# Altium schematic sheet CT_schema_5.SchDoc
size 388 x 258 mm
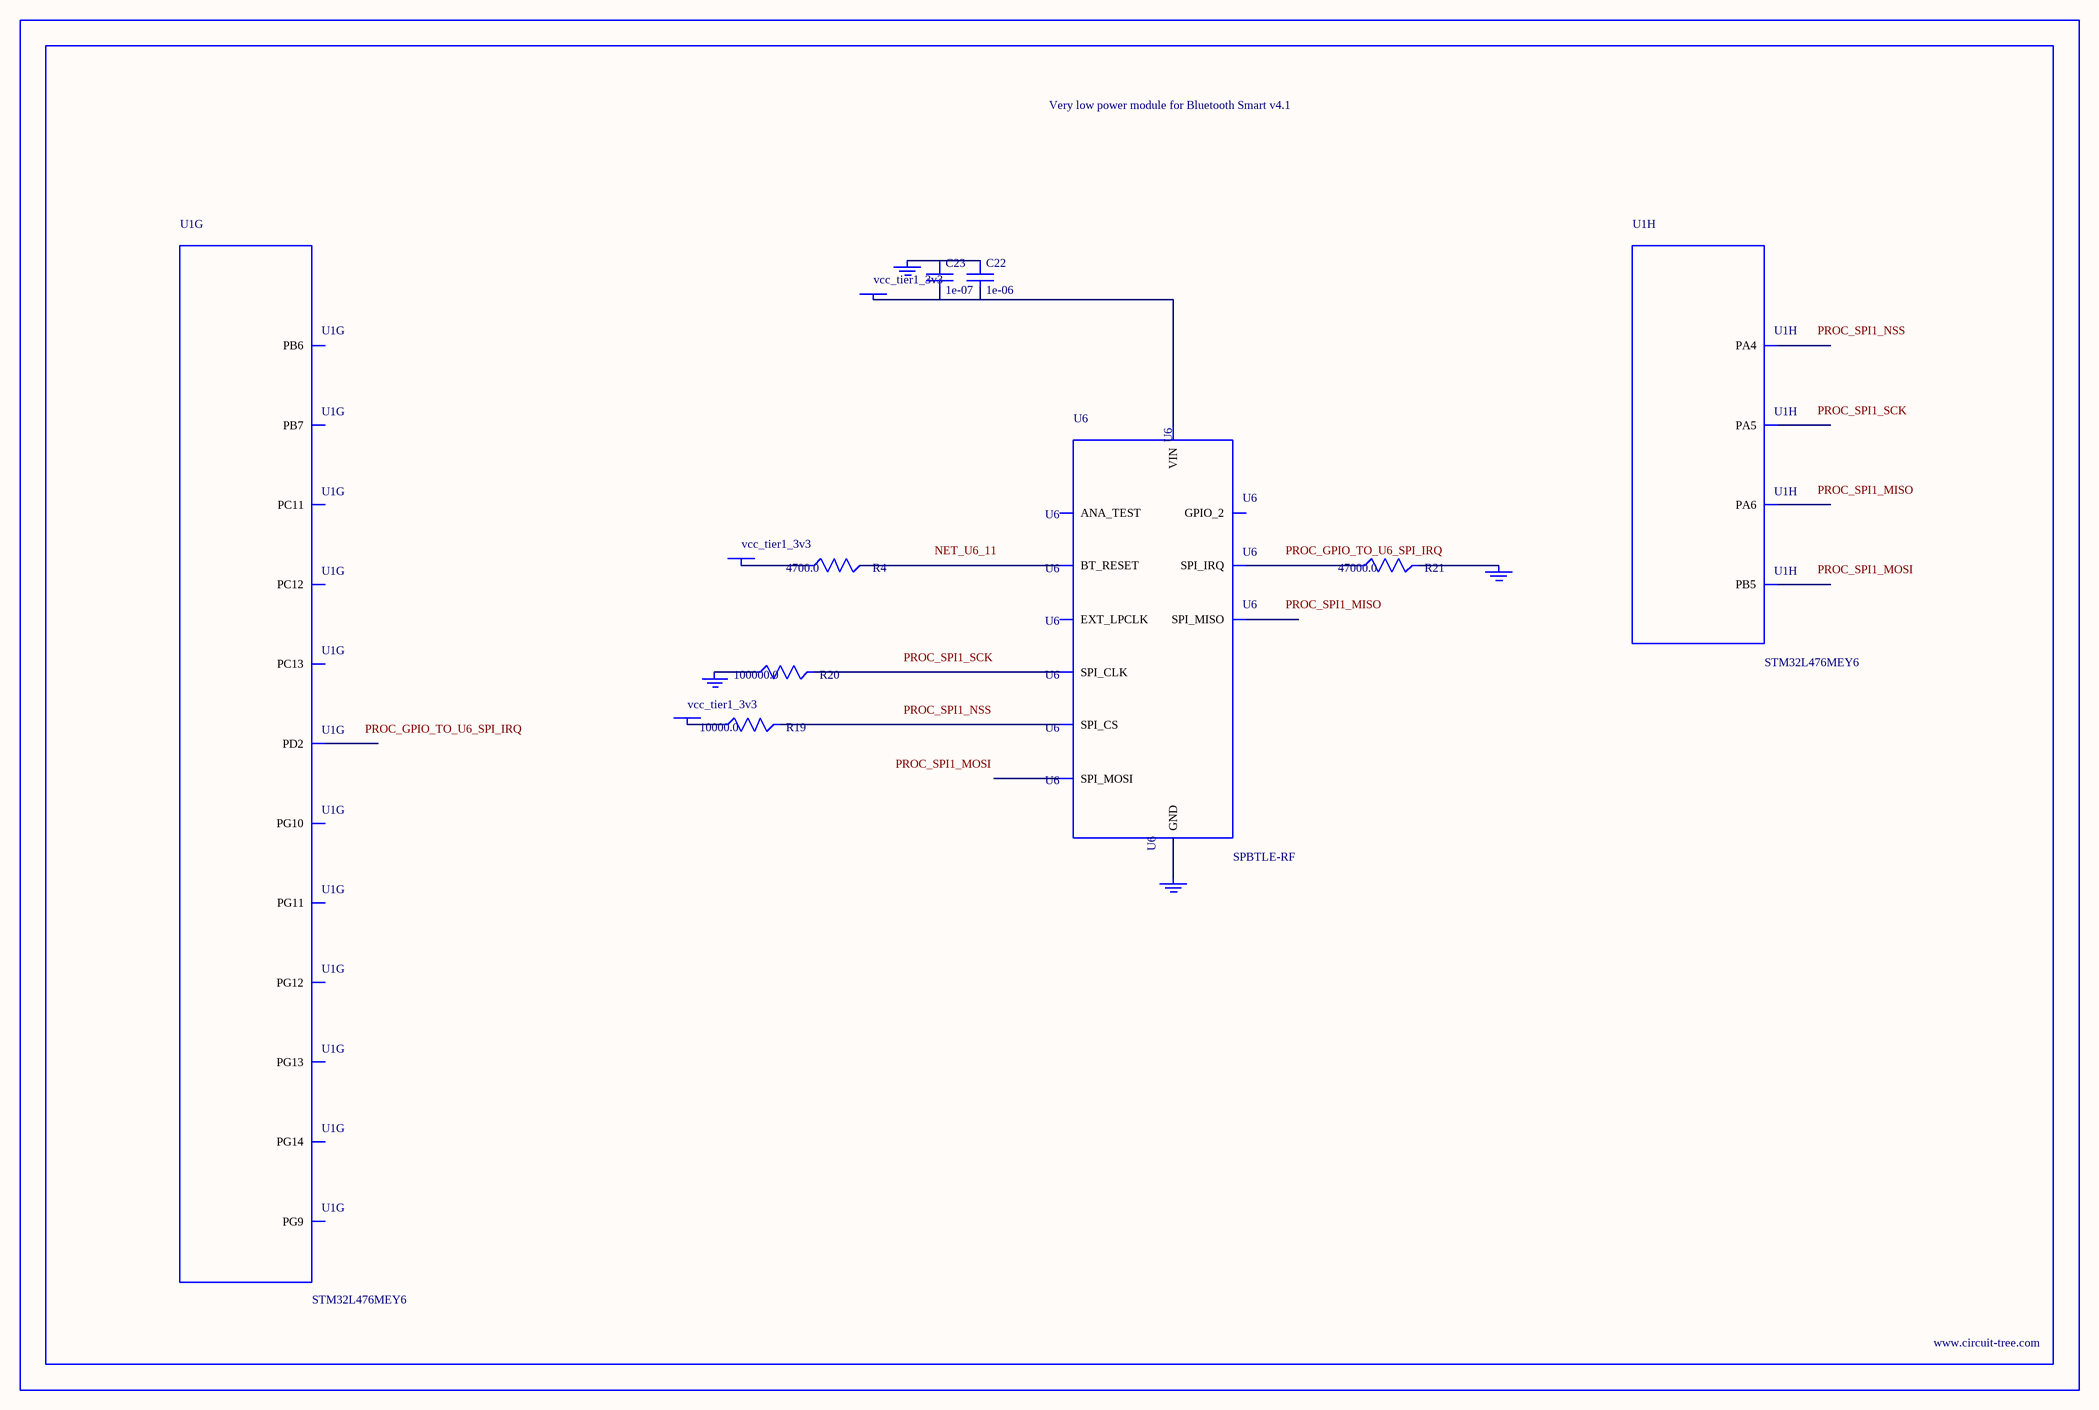
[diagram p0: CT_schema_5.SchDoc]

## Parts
BORDER4  (no value)
C22  1e-06  [C0603]
C23  1e-07  [C0402]
GND_INSTANCE_4_0  (no value)
GND_INSTANCE_4_1  (no value)
GND_INSTANCE_4_2  (no value)
GND_INSTANCE_4_3  (no value)
POWER_INSTANCE_4_0  vcc_tier1_3v3
POWER_INSTANCE_4_1  vcc_tier1_3v3
POWER_INSTANCE_4_2  vcc_tier1_3v3
R4  4700.0  [R0603]
R19  10000.0  [R0603]
R20  100000.0  [R0603]
R21  47000.0  [R0603]
U1  STM32L476MEY6  [WLCSP81]  (parts G,H of 9)
U6  SPBTLE-RF  [XCVR_SPBTLE-RF]

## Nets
NetC22_1: C22.1 C23.1 GND_INSTANCE_4_1.0(GND)
NetC22_2: C22.2 C23.2 POWER_INSTANCE_4_0.0(PWR) U6.5(VIN)
NetGND_INSTANCE_4_0_0: GND_INSTANCE_4_0.0(GND) R21.2
NetGND_INSTANCE_4_2_0: GND_INSTANCE_4_2.0(GND) R20.1
NetGND_INSTANCE_4_3_0: GND_INSTANCE_4_3.0(GND) U6.6(GND)
NetPOWER_INSTANCE_4_1_0: POWER_INSTANCE_4_1.0(PWR) R19.1
NetPOWER_INSTANCE_4_2_0: POWER_INSTANCE_4_2.0(PWR) R4.1
NetR4_2: R4.2 U6.11(BT_RESET)
NetR19_2: R19.2 U6.10(SPI_CS)
NetR20_2: R20.2 U6.7(SPI_CLK)
NetR21_1: R21.1 U6.4(SPI_IRQ)

Not connected (* = marked no-connect by the designer): U1 A3(PD2) A4(PG9) A5(PG14) A7(PB7) B3(PC12) B4(PG10) B5(PG13) B7(PB6) B8(PC13) C3(PC11) C4(PG11) C5(PG12) C7(PB5) G5(PA4) H5(PA6) H6(PA5); U6 1(EXT_LPCLK) 2(GPIO_2) 3(ANA_TEST) 8(SPI_MISO) 9(SPI_MOSI)

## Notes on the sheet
- Labels drawn without touching a wire or pin: NET_U6_11, PROC_GPIO_TO_U6_SPI_IRQ, PROC_SPI1_MISO, PROC_SPI1_MOSI, PROC_SPI1_NSS, PROC_SPI1_SCK

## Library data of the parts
BORDER4 = BORDER_PAGE4
C22 = C0603C105K3RACTU
C23 = C0402C104K3RACTU
GND_INSTANCE_4_0-GND_INSTANCE_4_3 = GND
POWER_INSTANCE_4_0-POWER_INSTANCE_4_2 = PWR
R4 = RC0603JR-074K7L
R19 = RC0603JR-0710KL
R20 = RC0603JR-07100KL
R21 = RC0603JR-0747KL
